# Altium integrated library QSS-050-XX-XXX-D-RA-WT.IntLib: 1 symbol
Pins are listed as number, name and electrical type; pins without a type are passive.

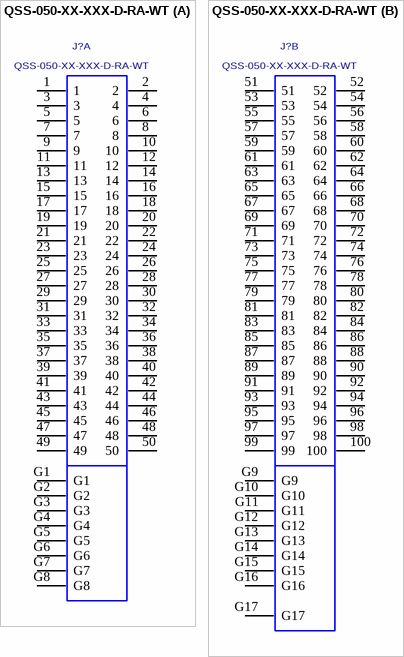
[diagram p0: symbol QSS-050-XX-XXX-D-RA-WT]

## QSS-050-XX-XXX-D-RA-WT
designator J?
.635mm DOUBLE ROW RIGHT ANGLE SOCKET STRIP WITH THREADED INSERT.; MANUFACTURER: SAMTEC
footprint QSS-050-XX-XXX-D-RA-WT
part A pins: 1, 2, 3, 4, 5, 6, 7, 8, 9, 10, 11, 12, 13, 14, 15, 16, 17, 18, 19, 20, 21, 22, 23, 24, 25, 26, 27, 28, 29, 30, 31, 32, 33, 34, 35, 36, 37, 38, 39, 40, 41, 42, 43, 44, 45, 46, 47, 48, 49, 50, G1, G2, G3, G4, G5, G6, G7, G8
part B pins: 51, 52, 53, 54, 55, 56, 57, 58, 59, 60, 61, 62, 63, 64, 65, 66, 67, 68, 69, 70, 71, 72, 73, 74, 75, 76, 77, 78, 79, 80, 81, 82, 83, 84, 85, 86, 87, 88, 89, 90, 91, 92, 93, 94, 95, 96, 97, 98, 99, 100, G9, G10, G11, G12, G13, G14, G15, G16, G17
